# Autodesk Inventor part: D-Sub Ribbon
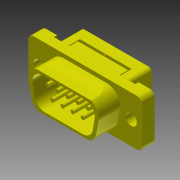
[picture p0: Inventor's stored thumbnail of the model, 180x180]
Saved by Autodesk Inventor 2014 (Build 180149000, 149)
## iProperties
Created: 2006-11
Document SubType Name: Modeling
Designer: floress
Categories: <MemberInstance><Categories><Category DisplayName="" Mnemonic="CABLEANDHARNESS" InternalName="e4a7e005-5e42-4d16-b293-125e7f0d0512"><Category DisplayName="" Mne
Density: 1 g/cm^3
Mass: 2.31161 g
Surface Area: 32.9407 cm^2
Volume: 2.31161 cm^3
Material: Generic
Appearance: Smooth - Yellow
Author: floress
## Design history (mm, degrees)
feature "Base1"
sketch "Sketch1"
  geometry: L1 (21.288, -8.458)-(6.55, -8.458) reference; L2 (21.288, -8.458)-(21.288, -2.54) reference; L3 (22.741, -2.54)-(21.288, -2.54) reference; L4 (22.741, -3.429)-(22.741, -2.54) reference; L5 (27.838, -3.429)-(22.741, -3.429) reference; L6 (27.838, 0)-(27.838, -3.429) reference; L7 (27.838, 0)-(0, 0) reference; L8 (0, 0)-(0, -3.429) reference; L9 (5.098, -3.429)-(0, -3.429) reference; L10 (5.098, -3.429)-(5.098, -2.54) reference; L11 (6.55, -2.54)-(5.098, -2.54) reference; L12 (6.55, -8.458)-(6.55, -2.54) reference; L13 (8.179, -5.588)-(8.179, -2.54) reference; L14 (8.395, -2.54)-(8.179, -2.54) reference; L15 (8.395, -2.54)-(8.395, -4.826) reference; L16 (19.444, -4.826)-(8.395, -4.826) reference; L17 (19.444, -2.54)-(19.444, -4.826) reference; L18 (19.66, -2.54)-(19.444, -2.54) reference; L19 (19.66, -5.588)-(19.66, -2.54) reference; L20 (8.179, -5.588)-(19.66, -5.588) reference; 1 further point
  constraints: 1 other
node "1"
node "2"
node "3"
node "4"
node "5"
node "6"
node "7"
node "8"
node "9"
sketch "Sketch2"
  geometry: L1 (5.296, 8.458)-(22.542, 8.458) reference; L2 (5.296, 8.458)-(5.296, 2.54) reference; L3 (5.296, 2.54)-(2.876, 2.54) reference; L4 (2.876, 3.429)-(2.876, 2.54) reference; L5 (0, 3.429)-(2.876, 3.429) reference; L6 (0, 0)-(0, 3.429) reference; L7 (0, 0)-(27.838, 0) reference; L8 (27.838, 0)-(27.838, 3.429) reference; L9 (24.962, 3.429)-(27.838, 3.429) reference; L10 (24.962, 3.429)-(24.962, 2.54) reference; L11 (24.962, 2.54)-(22.542, 2.54) reference; L12 (22.542, 8.458)-(22.542, 2.54) reference; L13 (20.93, 5.588)-(20.93, 2.54) reference; L14 (20.93, 2.54)-(20.714, 2.54) reference; L15 (20.714, 2.54)-(20.714, 4.826) reference; L16 (7.125, 4.826)-(20.714, 4.826) reference; L17 (7.125, 2.54)-(7.125, 4.826) reference; L18 (7.125, 2.54)-(6.909, 2.54) reference; L19 (6.909, 5.588)-(6.909, 2.54) reference; L20 (20.93, 5.588)-(6.909, 5.588) reference; L21 (13.919, 5.588)-(13.919, 4.826); 2 further points
  constraints: 3 midpoint, 2 end point, 1 coincident
workpoint "Work Point10"
body "Solid1"
